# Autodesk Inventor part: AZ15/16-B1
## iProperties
Created: 2006-08
Part Number: AZ15/16-B1
Material: Kst - PE/UHMW - Schwarz
Document SubType Name: Modellieren
Designer: TMT
Manufacturer: Standard
Standards Organization: Custom
Description: Schlüssel
Author: TMT
Comments: SCHMERSAL
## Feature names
1. Basis1
